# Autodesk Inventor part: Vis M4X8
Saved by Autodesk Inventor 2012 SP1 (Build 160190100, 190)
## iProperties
Created: 2014-12
Part Number: Vis M4X8
Material: Default
Document SubType Name: Modeling
Designer: Bruno
Density: 1 g/cm^3
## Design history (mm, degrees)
node "Vis M4X81"
node "Vis M4X8"
node "Base1"
